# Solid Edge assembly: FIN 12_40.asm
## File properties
Title: Zylinder
Author: bmolnar
Template: iso assembly.asm
Last saved by: bmolnar
Revision: 14
Application: Solid Edge
Username: bmolnar
Dokumentum tartalom típus: 1
Document Number: FIN 12/40
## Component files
Kolbenstange.par
Profilrohr.par
Kit.par
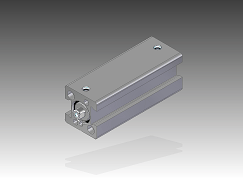
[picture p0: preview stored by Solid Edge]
